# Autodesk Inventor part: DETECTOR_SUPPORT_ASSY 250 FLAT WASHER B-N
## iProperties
Shininess: 64.0
Length Units: 11272
Angle Units: 11279
Time Units: 11290
Mass Units: 11286
Length Display Precision: 3
Angle Display Precision: 2
Compacted: True
Part Number: DETECTOR_SUPPORT_ASSY 250 FLAT WASHER B-N
Document SubType Name: Modeling
Created: 2004-08
Designer: John Blackburn
Material: STAINLESS_STEEL, AUSTENITIC
Manufacturer: Standard
Standards Organization: Custom
Density: 0.0
Volumn: 0.0
Area: 0.0
PropertySet Name: Model Information
Control State: 0
Master: False
Checked Out: False
Author: John Blackburn
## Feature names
1. Base1
